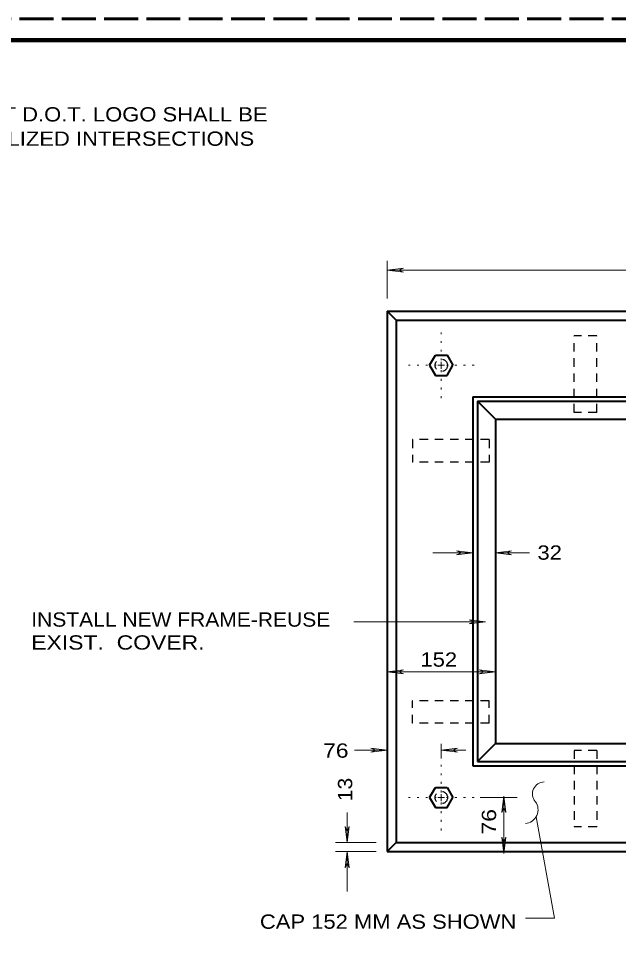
# Model space of a CAD drawing. Extents: x 312583 to 312853, y 144419 to 144586.
# Drawn here: x 312701.41 to 312733.29, y 144536.44 to 144586.22 of the extents above; entities that cross this region are included whole.
import ezdxf

# ---------------------------------------------------------------- set-up
doc = ezdxf.new("R2010")
doc.units = 0
doc.header["$LTSCALE"] = 0.3
for name, pattern in [('DOTTED', [1.5, 0.3, -1.2]), ('LONG_DASHED', [7.5, 6, -1.5]), ('SHORT_DASHED', [2.7, 1.5, -1.2])]:
    doc.linetypes.add(name, pattern=pattern)
doc.layers.add('1', color=7, linetype='Continuous', lineweight=40)
doc.layers.add('2', color=7, linetype='Continuous', lineweight=13)

msp = doc.modelspace()

# ---------------------------------------------------------------- linework, layer by layer
at = {"layer": '1', "linetype": 'LONG_DASHED', "lineweight": 60}
msp.add_line((312851.75, 144586.2246), (312583.526, 144586.2246), dxfattribs=at)
msp.add_line((312851.75, 144586.2246), (312583.526, 144586.2246), dxfattribs=at)
at = {"layer": '1'}
for p, q in [((312721.0054, 144570.6589), (312767.0054, 144570.6589)), ((312721.0054, 144570.6589), (312721.0054, 144541.9089)), ((312721.0054, 144570.6589), (312721.4807, 144570.1759)), ((312721.4807, 144570.1759), (312721.4807, 144542.3842)), ((312723.2594, 144567.7839), (312723.566, 144568.3206)), ((312723.2594, 144567.7839), (312723.566, 144567.2472)), ((312724.187, 144567.2472), (312724.5014, 144567.7839)), ((312723.566, 144567.2472), (312724.187, 144567.2472)), ((312725.5594, 144566.1049), (312725.5594, 144546.4629)), ((312725.797, 144565.8672), (312725.797, 144546.7006)), ((312725.797, 144565.8672), (312726.7554, 144564.9089)), ((312726.7554, 144564.9089), (312747.9307, 144564.9089)), ((312726.7554, 144547.6589), (312725.797, 144546.7006)), ((312725.5594, 144546.4629), (312762.4514, 144546.4629)), ((312725.797, 144546.7006), (312762.2137, 144546.7006)), ((312723.2594, 144544.7839), (312723.566, 144545.3206)), ((312723.566, 144545.3206), (312724.187, 144545.3206)), ((312724.187, 144545.3206), (312724.5014, 144544.7839)), ((312723.2594, 144544.7839), (312723.566, 144544.2472)), ((312721.4807, 144542.3842), (312721.0054, 144541.9089)), ((312721.4807, 144542.3842), (312766.5224, 144542.3842)), ((312721.0054, 144541.9089), (312767.0054, 144541.9089))]:
    msp.add_line(p, q, dxfattribs=at)
at = {"layer": '1', "linetype": 'SHORT_DASHED', "lineweight": 25}
for p, q in [((312732.145, 144569.3479), (312730.949, 144569.3479)), ((312730.949, 144565.2769), (312730.949, 144569.3479)), ((312732.145, 144565.2769), (312732.145, 144569.3479)), ((312732.145, 144565.2769), (312730.949, 144565.2769)), ((312722.3547, 144563.8279), (312722.3547, 144562.6319)), ((312726.418, 144563.8279), (312722.3547, 144563.8279)), ((312726.418, 144563.8279), (312726.418, 144562.6319)), ((312726.418, 144562.6319), (312722.3547, 144562.6319)), ((312722.3547, 144548.7399), (312722.3547, 144549.9359)), ((312726.418, 144549.9359), (312722.3547, 144549.9359)), ((312726.418, 144548.7399), (312726.418, 144549.9359)), ((312726.418, 144548.7399), (312722.3547, 144548.7399)), ((312732.145, 144547.2909), (312730.949, 144547.2909)), ((312730.949, 144547.2909), (312730.949, 144543.2199)), ((312732.145, 144547.2909), (312732.145, 144543.2199)), ((312732.145, 144543.2199), (312730.949, 144543.2199))]:
    msp.add_line(p, q, dxfattribs=at)
at = {"layer": '1', "lineweight": 158}
msp.add_lwpolyline([(312616.5, 144423.1446), (312616.5, 144585.0846), (312849, 144585.0846)], dxfattribs=at)
at = {"layer": '1'}
for points in [[(312721.4807, 144570.1759), (312766.5224, 144570.1759), (312766.5224, 144542.3842)], [(312723.566, 144568.3206), (312724.187, 144568.3206), (312724.5014, 144567.7839)], [(312725.5594, 144566.1049), (312762.4514, 144566.1049), (312762.4514, 144546.4629)], [(312725.797, 144565.8672), (312762.2137, 144565.8672), (312762.2137, 144546.7006)], [(312726.7554, 144564.9089), (312726.7554, 144547.6589), (312761.2554, 144547.6589)], [(312723.566, 144544.2472), (312724.187, 144544.2472), (312724.5014, 144544.7839)]]:
    msp.add_lwpolyline(points, dxfattribs=at)
at = {"layer": '1', "linetype": 'SHORT_DASHED', "lineweight": 25}
for centre in [(312723.8785, 144567.7829), (312723.8785, 144544.7829)]:
    msp.add_circle(centre, 0.3301, dxfattribs=at)
at = {"layer": '2'}
for p, q in [((312721.0054, 144571.3336), (312721.0054, 144573.3346)), ((312721.0054, 144572.8439), (312721.8717, 144572.9512)), ((312721.0054, 144572.8439), (312767.0054, 144572.8439)), ((312721.0054, 144572.8439), (312721.8717, 144572.7366)), ((312721.8717, 144572.9512), (312721.5957, 144572.8439)), ((312721.8717, 144572.7366), (312721.5957, 144572.8439)), ((312723.8804, 144567.7839), (312723.6964, 144567.7839)), ((312723.8804, 144567.7839), (312723.8804, 144567.9602)), ((312723.8804, 144567.7839), (312724.0567, 144567.7839)), ((312723.8804, 144567.7839), (312723.8804, 144567.5999)), ((312723.428, 144557.8019), (312725.5594, 144557.8019)), ((312724.693, 144557.9092), (312724.969, 144557.8019)), ((312725.5594, 144557.8019), (312724.693, 144557.9092)), ((312724.693, 144557.6946), (312724.969, 144557.8019)), ((312725.5594, 144557.8019), (312724.693, 144557.6946)), ((312726.7554, 144557.8019), (312727.6217, 144557.9092)), ((312726.7554, 144557.8019), (312728.5647, 144557.8019)), ((312726.7554, 144557.8019), (312727.6217, 144557.6946)), ((312727.6217, 144557.9092), (312727.3457, 144557.8019)), ((312727.6217, 144557.6946), (312727.3457, 144557.8019)), ((312725.3677, 144554.2446), (312725.6437, 144554.1372)), ((312726.234, 144554.1372), (312725.3677, 144554.2446)), ((312719.2267, 144554.1372), (312726.234, 144554.1372)), ((312725.3677, 144554.0299), (312725.6437, 144554.1372)), ((312726.234, 144554.1372), (312725.3677, 144554.0299)), ((312721.0054, 144551.4769), (312721.8717, 144551.5842)), ((312721.0054, 144551.4769), (312726.7554, 144551.4769)), ((312721.0054, 144551.4769), (312721.8717, 144551.3696)), ((312721.8717, 144551.5842), (312721.5957, 144551.4769)), ((312721.8717, 144551.3696), (312721.5957, 144551.4769)), ((312725.889, 144551.5842), (312726.165, 144551.4769)), ((312726.7554, 144551.4769), (312725.889, 144551.5842)), ((312725.889, 144551.3696), (312726.165, 144551.4769)), ((312726.7554, 144551.4769), (312725.889, 144551.3696)), ((312719.2574, 144547.3062), (312721.0054, 144547.3062)), ((312720.139, 144547.4136), (312720.415, 144547.3062)), ((312721.0054, 144547.3062), (312720.139, 144547.4136)), ((312720.139, 144547.1989), (312720.415, 144547.3062)), ((312721.0054, 144547.3062), (312720.139, 144547.1989)), ((312723.8804, 144546.8539), (312723.8804, 144547.6436)), ((312723.8804, 144547.3062), (312724.7467, 144547.4136)), ((312723.8804, 144547.3062), (312725.1914, 144547.3062)), ((312723.8804, 144547.3062), (312724.7467, 144547.1989)), ((312724.7467, 144547.4136), (312724.4707, 144547.3062)), ((312724.7467, 144547.1989), (312724.4707, 144547.3062)), ((312723.8804, 144544.7839), (312723.6964, 144544.7839)), ((312723.8804, 144544.7839), (312723.8804, 144544.9602)), ((312723.8804, 144544.7839), (312724.0567, 144544.7839)), ((312723.8804, 144544.7839), (312723.8804, 144544.5999)), ((312725.9427, 144544.7839), (312727.9207, 144544.7839)), ((312727.2, 144544.8522), (312727.0927, 144543.9859)), ((312727.2, 144544.8522), (312727.3074, 144543.9859)), ((312727.2, 144541.9089), (312727.2, 144544.7839)), ((312727.0927, 144543.9859), (312727.2, 144544.2619)), ((312727.3074, 144543.9859), (312727.2, 144544.2619)), ((312718.874, 144542.3842), (312718.874, 144543.9866)), ((312718.7667, 144543.2506), (312718.874, 144542.9746)), ((312718.874, 144542.3842), (312718.7667, 144543.2506)), ((312718.9814, 144543.2506), (312718.874, 144542.9746)), ((312718.874, 144542.3842), (312718.9814, 144543.2506)), ((312720.415, 144542.3842), (312718.253, 144542.3842)), ((312727.0927, 144542.6715), (312727.2, 144542.3955)), ((312727.2, 144541.8052), (312727.0927, 144542.6715)), ((312727.3074, 144542.6715), (312727.2, 144542.3955)), ((312727.2, 144541.8052), (312727.3074, 144542.6715)), ((312720.415, 144541.9089), (312718.253, 144541.9089)), ((312718.874, 144541.9089), (312718.7667, 144541.0426)), ((312718.874, 144539.7852), (312718.874, 144541.9089)), ((312718.874, 144541.9089), (312718.9814, 144541.0426)), ((312718.7667, 144541.0426), (312718.874, 144541.3186)), ((312718.9814, 144541.0426), (312718.874, 144541.3186))]:
    msp.add_line(p, q, dxfattribs=at)
at = {"layer": '2', "linetype": 'DOTTED'}
for p, q in [((312723.8804, 144568.0522), (312723.8804, 144569.8539)), ((312723.612, 144567.7839), (312721.8104, 144567.7839)), ((312724.1487, 144567.7839), (312725.9427, 144567.7839)), ((312723.8804, 144567.5156), (312723.8804, 144565.7139)), ((312723.8804, 144545.0522), (312723.8804, 144546.8539)), ((312723.612, 144544.7839), (312721.8104, 144544.7839)), ((312724.1487, 144544.7839), (312725.9427, 144544.7839)), ((312723.8804, 144544.5156), (312723.8804, 144542.7139))]:
    msp.add_line(p, q, dxfattribs=at)
at = {"layer": '2'}
msp.add_lwpolyline([(312728.3654, 144538.3592), (312729.8987, 144538.3592), (312728.925, 144543.7566)], dxfattribs=at)
for centre, radius, start, end in [((312729.3649, 144544.9818), 0.6341, 91.07374, 220.22244), ((312728.2917, 144544.1327), 0.735, 274.68748, 36.73556)]:
    msp.add_arc(centre, radius, start, end, dxfattribs=at)

# ---------------------------------------------------------------- texts
for s, width, p in [('JUNCTION BOX COVER WITHOUT D.O.T. LOGO SHALL BE', 1.15, (312682.3025, 144580.7562)), ('UTILIZED FOR ALL LOCAL SIGNALIZED INTERSECTIONS', 1.15, (312682.3025, 144579.4628)), ('32 ', 1.15, (312728.994, 144557.4399)), ('INSTALL NEW FRAME-REUSE', 1.1, (312702.072, 144553.8756)), ('EXIST.  COVER.', 1.2, (312702.072, 144552.6556)), ('152 ', 1.15, (312722.7712, 144551.7472)), ('76 ', 1.2, (312717.5907, 144546.9035)), ('CAP 152 MM AS SHOWN', 1.15, (312714.2327, 144537.8015))]:
    msp.add_text(s, height=0.76, dxfattribs=dict(at, width=width)).set_placement(p)
for s, width, p in [('13 ', 1.1, (312719.1423, 144544.5908)), ('76 ', 1.2, (312726.7953, 144542.8171))]:
    msp.add_text(s, height=0.76, rotation=90, dxfattribs=dict(at, width=width)).set_placement(p)

doc.saveas('drawing.dxf')
